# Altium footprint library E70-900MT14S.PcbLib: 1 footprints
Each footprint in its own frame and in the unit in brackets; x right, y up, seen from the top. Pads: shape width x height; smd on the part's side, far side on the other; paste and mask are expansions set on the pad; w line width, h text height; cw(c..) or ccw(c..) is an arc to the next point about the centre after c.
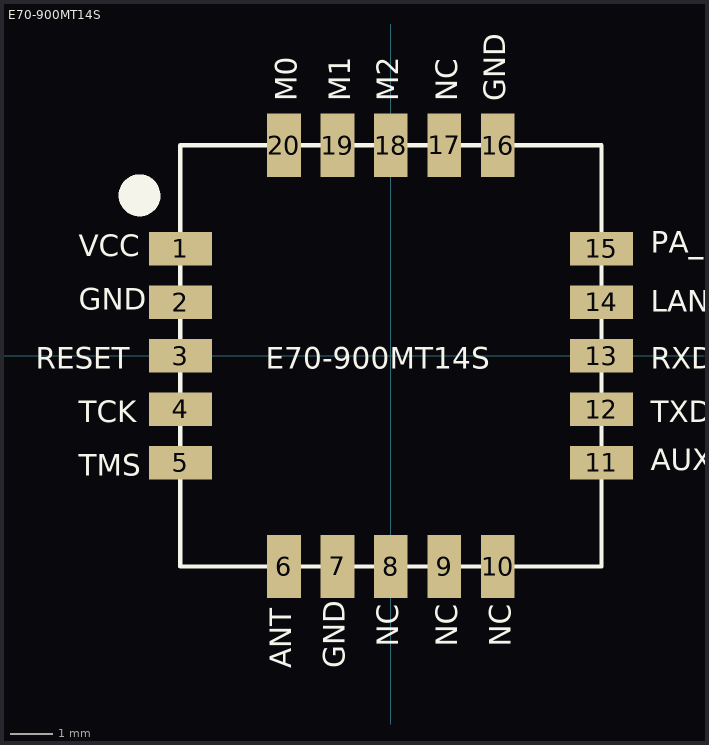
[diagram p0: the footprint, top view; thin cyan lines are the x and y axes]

## E70-900MT14S [mm] "E70-900MT14S"
pads (20):
  rect 1.5x0.8 smd mask+0.102: 1(-5,2.54) 2(-5,1.27) 3(-5,0) 4(-5,-1.27) 5(-5,-2.54) 11(5,-2.54) 12(5,-1.27) 13(5,0) 14(5,1.27) 15(5,2.54)
  rect 0.8x1.5 smd mask+0.102: 6(-2.54,-5) 7(-1.27,-5) 8(0,-5) 9(1.27,-5) 10(2.54,-5) 16(2.54,5) 17(1.27,5) 18(0,5) 19(-1.27,5) 20(-2.54,5)
Top Overlay:
  lines w0.1: -5,-5 -5,5 5,5 5,-5 -5,-5
  lines w0.635: -5.808,3.89 ccw(c-5.969,3.81) -5.789,3.81
  text "E70-900MT14S" at -2.972,-0.305 h0.51
  text "VCC" at -7.417,2.362 h0.51
  text "GND" at -7.417,1.092 h0.51
  text "RESET" at -8.432,-0.305 h0.51
  text "TCK" at -7.417,-1.575 h0.51
  text "TMS" at -7.417,-2.845 h0.51
  text "ANT" at -2.362,-7.417 h0.51
  text "GND" at -1.092,-7.417 h0.51
  text "NC" at 0.178,-6.909 h0.51
  text "NC" at 1.575,-6.909 h0.51
  text "NC" at 2.845,-6.909 h0.51
  text "AUX" at 6.172,-2.718 h0.51
  text "TXD" at 6.172,-1.575 h0.51
  text "RXD" at 6.172,-0.305 h0.51
  text "LAN_EN" at 6.172,1.05 h0.51
  text "PA_EN" at 6.172,2.447 h0.51
  text "GND" at 2.718,6.045 h0.51
  text "NC" at 1.575,6.045 h0.51
  text "M2" at 0.178,6.045 h0.51
  text "M1" at -0.965,6.045 h0.51
  text "M0" at -2.235,6.045 h0.51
